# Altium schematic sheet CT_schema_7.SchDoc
size 305 x 256 mm
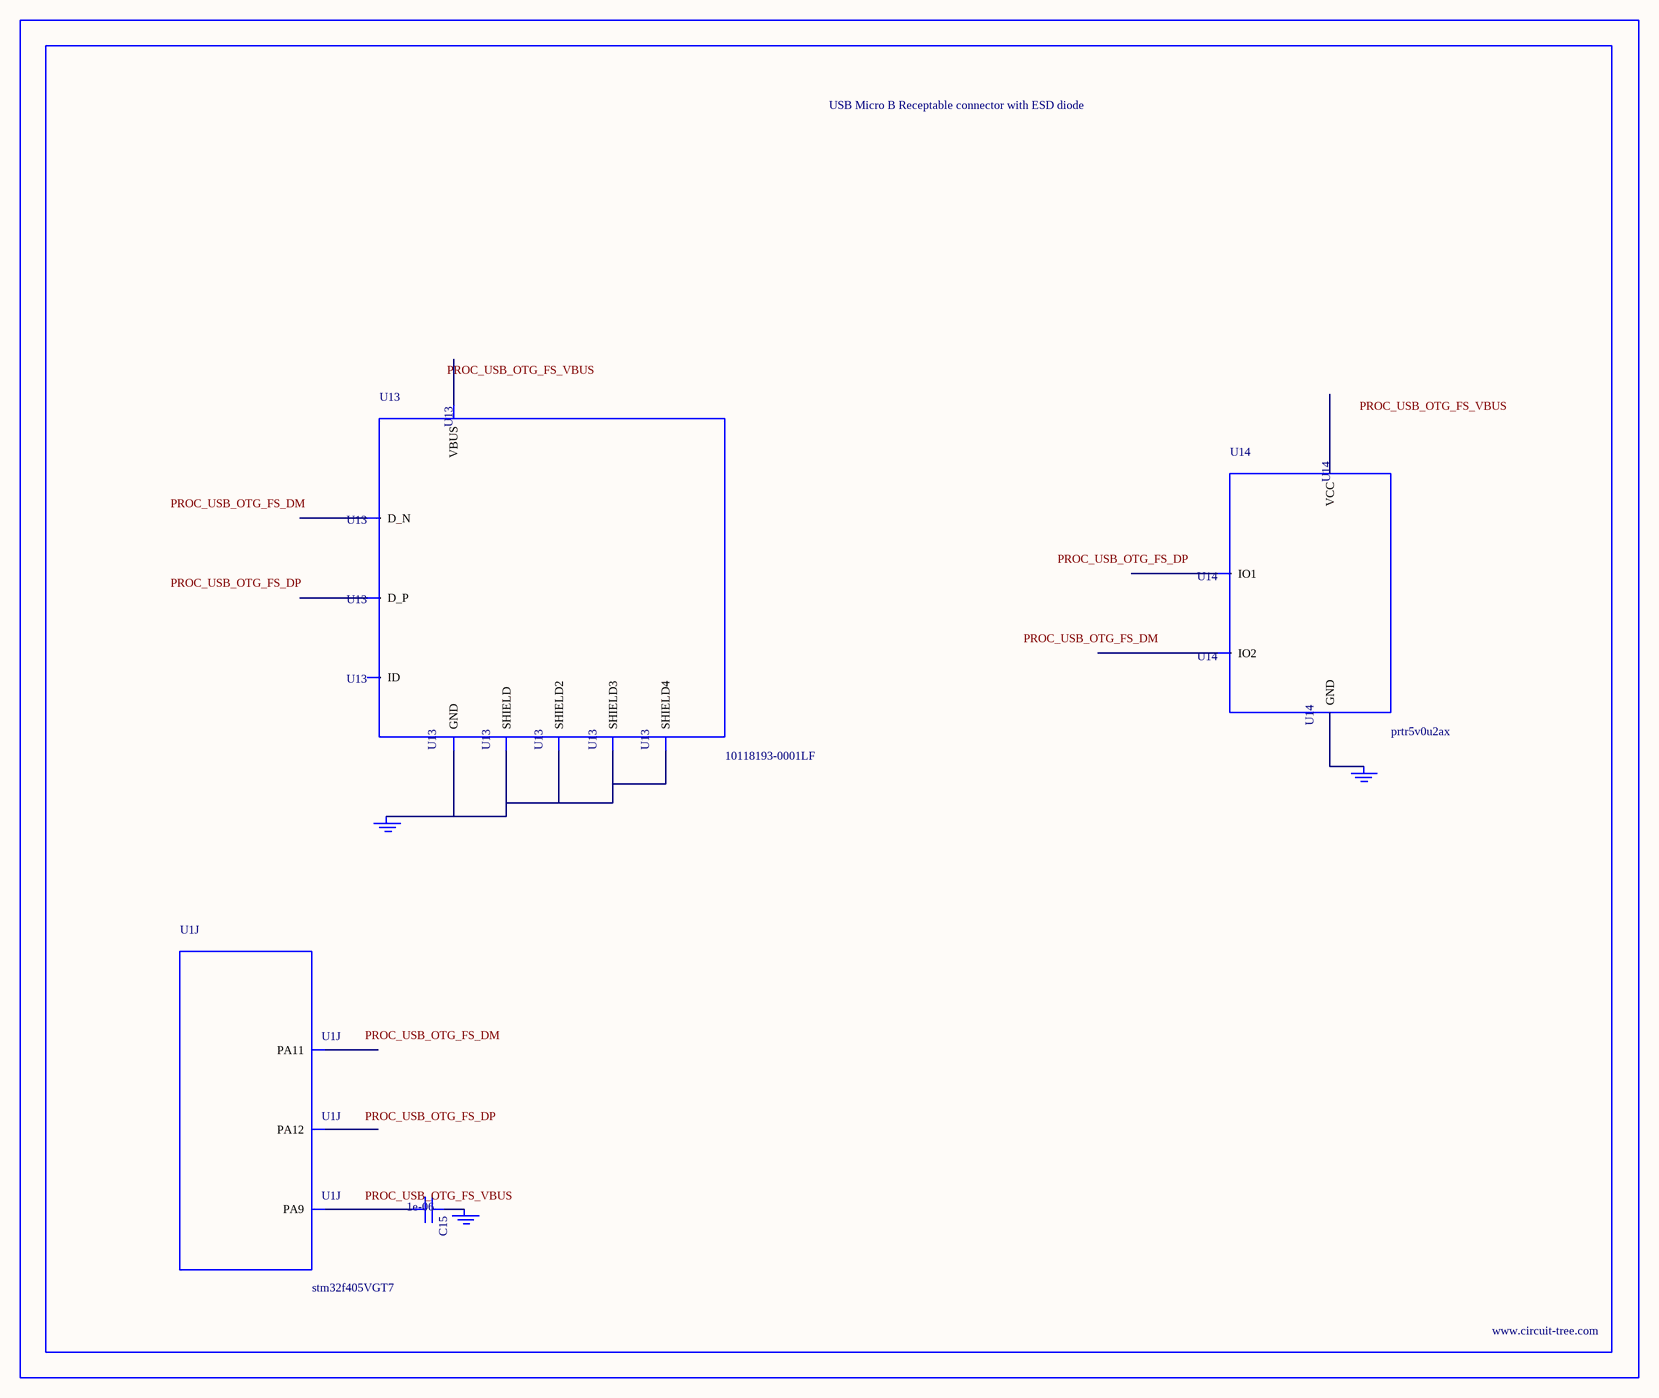
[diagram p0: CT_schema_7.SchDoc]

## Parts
BORDER6  (no value)
C15  1e-06  [C0603]
GND_INSTANCE_6_0  (no value)
GND_INSTANCE_6_1  (no value)
GND_INSTANCE_6_2  (no value)
U1  stm32f405VGT7  [LQFP100]  (part J of 10)
U13  10118193-0001LF  [FCI_10118193-0001LF]
U14  prtr5v0u2ax  [SOT143B]

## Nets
NetC15_1: C15.1 GND_INSTANCE_6_1.0(GND)
NetC15_2: C15.2 U1.68(PA9)
NetGND_INSTANCE_6_0_0: GND_INSTANCE_6_0.0(GND) U13.5(GND) U13.6(SHIELD) U13.7(SHIELD2) U13.8(SHIELD3) U13.9(SHIELD4)
NetGND_INSTANCE_6_2_0: GND_INSTANCE_6_2.0(GND) U14.1(GND)

Not connected (* = marked no-connect by the designer): U1 70(PA11) 71(PA12); U13 1(VBUS) 2(D_N) 3(D_P) 4(ID); U14 2(IO1) 3(IO2) 4(VCC)

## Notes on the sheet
- Labels drawn without touching a wire or pin: PROC_USB_OTG_FS_DM, PROC_USB_OTG_FS_DP, PROC_USB_OTG_FS_VBUS

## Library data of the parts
BORDER6 = BORDER_PAGE6
C15 = C0603C105K3RACTU
GND_INSTANCE_6_0-GND_INSTANCE_6_2 = GND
